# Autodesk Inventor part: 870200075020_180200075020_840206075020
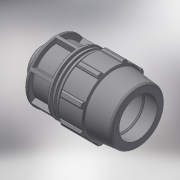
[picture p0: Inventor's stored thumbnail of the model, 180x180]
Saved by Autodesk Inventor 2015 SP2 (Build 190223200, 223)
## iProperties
Created: 2017-02
Part Number: 870200075020_180200075020_840206075020
Material: Generic
Description: PLASSON MALE ADAPTOR 75-2"
Document SubType Name: Modeling
Designer: KIM
Mass: 964.158 g
Surface Area: 1468.9 cm^2
Volume: 964.158 cm^3
Density: 1 g/cm^3
Appearance: Default
Author: KIM
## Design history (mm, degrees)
derived "87020.ipt"
feature "Solid1::87020.ipt"
tag "TaggingFeature1"
body "Solid1"
other parameters: "d2" = 75, "d4" = 27, "d5" = 47.25, "d7" = 132, "d8" = 99, "d9" = 27, "d11" = 5.4, "d12" = 105.6, "d13" = 120 deg, "d14" = 105, "d15" = 6 deg, "d16" = 118.8, "d18" = 3.75, "d19" = 35 deg, "d20" = 17.5 deg, "d21" = 122.76, "d23" = 0, "d25" = 360 deg, "d27" = 2.64, "d34" = 6.6, "d36" = 0, "d42" = 47.25, "d43" = 3.96, "d46" = 2.25, "d49" = 156, "d51" = 189, "d52" = 26, "d53" = 1.5, "d55" = 360 deg, "d57" = 59.614, "d58" = 41.7298, "d59" = 37.8, "d61" = 116.424, "d62" = 3.98, "d63" = 3.98, "d66" = 7.96, "d_" = 75, "E_" = 132, "H_" = 189, "l_" = 156, "l_2" = 26, "R_" = 59.614, "d60" = 19.9
